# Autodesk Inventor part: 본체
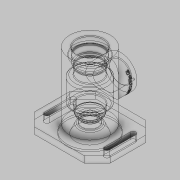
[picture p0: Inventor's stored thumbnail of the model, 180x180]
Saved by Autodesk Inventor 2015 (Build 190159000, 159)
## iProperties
Created: 2017-10
Part Number: 본체
Material: 일반
Document SubType Name: Modeling
Designer: SCD-A15
Density: 1 g/cm^3
Appearance: 기본값
Author: SCD-A15
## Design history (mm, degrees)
sketch "스케치1"
  geometry: L1 (31, 57.5)-(0, 57.5); L2 (0, 57.5)-(0, -57.5); L3 (0, -57.5)-(31, -57.5); L4 (31, -57.5)-(31, 57.5); 2 further points
  constraints: 8 end point, 2 coincident, 2 parallel, 1 horizontal, 1 midpoint, 1 perpendicular
  dimensions: "d0" = 115 distance of L3.end L1.start; "d2" = 62 diameter of L4 L2
revolve "회전1" sketch "스케치1" stored, may be unused: angle "d3" = 90 deg
sketch "스케치2"
  geometry: L1 (-58, 47)-(58, 47); L2 (58, 47)-(58, -47); L3 (58, -47)-(-58, -47); L4 (-58, -47)-(-58, 47); C1 r 31 at (0, 0) reference; 2 further points
  constraints: 8 end point, 2 midpoint, 2 parallel, 1 horizontal, 1 horizontal alignment, 1 perpendicular, 1 vertical alignment
  dimensions: "d5" = 116 distance of L1.start L1.end; "d6" = 94 distance of L3.end L1.start
extrude "돌출1" join sketch "스케치2" distance "d7" = 13; taper "d8" = 0 deg
sketch "스케치3"
  geometry: L1 (0, 0)-(116, 0) reference; L2 (0, -94)-(0, 0) reference; L3 (116, -94)-(0, -94) reference; L4 (116, 0)-(116, -94) reference; C1 r 35 at (58, -47); 1 further point
  constraints: 1 centre point, 1 coincident
  dimensions: "d9" = 70 diameter of C1
extrude "돌출2" cut sketch "스케치3" distance "d10" = 3; taper "d11" = 0 deg
node "작업 평면2"
  node "작업 평면1"
sketch "스케치4"
  geometry: L1 (89, -102)-(27, -102) reference; C1 r 25 at (58, -46); 2 further points
  constraints: 1 centre point, 1 midpoint, 1 vertical alignment
  dimensions: "d13" = 50 diameter of C1; "d14" = 56 distance from line of L1 C1.centre
extrude "돌출3" join sketch "스케치4" stored distance "d15" = 47 (= d12); taper "d16" = 0 deg
sketch "스케치5" dims "d17" = 8, "d18" = 8
  geometry: L1 (46.253, 16.008)-(46.154, 16.008); L2 (46.154, -16.003)-(46.253, -16.003); C1 r 31 at (0, 0) reference; 2 further points
  constraints: 4 end point, 1 horizontal, 1 parallel, 1 vertical alignment, 6 other
  dimensions: "d19" = 46 horizontal distance of C1.centre point (46, -20); "d20" = 20 vertical distance of C1.centre point (46, -20); "d22" = 20 vertical distance of point (46, 20) C1.centre
extrude "돌출4" cut sketch "스케치5" distance "d23" = 47 (= d12); taper "d24" = 0 deg
sketch "스케치6"
  geometry: L1 (42, 20)-(50, 20); L2 (50, 20)-(50, -20); L3 (50, -20)-(42, -20); L4 (42, -20)-(42, 20); 2 further points
  constraints: 8 end point, 2 horizontal alignment, 2 parallel, 1 horizontal, 1 perpendicular, 2 other
extrude "돌출5" cut sketch "스케치6" distance "d25" = 47 (= d12); taper "d26" = 0 deg
hole "구멍1" diameter "d29" = 40.376; stored, may be unused: countersink angle "d33" = 90 deg, drill point angle "d35" = 0 deg; dims "d30" = 84, "d31" = 4, "d32" = 2, "d34" = 9, "d55" = 10, "d56" = 10
hole "구멍2" diameter "d38" = 48; stored, may be unused: countersink angle "d42" = 90 deg, drill point angle "d44" = 0 deg; dims "d36" = 10, "d37" = 10, "d39" = 84, "d40" = 4, "d41" = 2, "d43" = 3
sketch "스케치9"
  geometry: L1 (-35, -57.5)-(-35, -54.5) reference; L2 (-35, -54.5)-(-47, -54.5) reference; L3 (-47, -54.5)-(-47, -44.5) reference; L4 (-47, -44.5)-(-31, -44.5) reference; L5 (-31, -44.5)-(-31, 57.5) reference; L6 (-31, 57.5)-(-20.188, 57.5) reference; L7 (-20.188, 57.5)-(-20.188, 48.5) reference; L8 (-20.188, 48.5)-(-24, 48.5) reference; L9 (-24, 48.5)-(-24, 45.5) reference; L10 (-24, 45.5)-(24, 45.5) reference; L11 (24, 45.5)-(24, 48.5) reference; L12 (24, 48.5)-(20.188, 48.5) reference; L13 (20.188, 48.5)-(20.188, 57.5) reference; L14 (20.188, 57.5)-(31, 57.5) reference; L15 (31, 57.5)-(31, 26.5) reference; L16 (31, 26.5)-(47, 26.5) reference; L17 (47, 26.5)-(47, -23.5) reference; L18 (47, -23.5)-(31, -23.5) reference; L19 (31, -23.5)-(31, -44.5) reference; L20 (31, -44.5)-(47, -44.5) reference; L21 (47, -44.5)-(47, -54.5) reference; L22 (47, -54.5)-(35, -54.5) reference; L23 (35, -54.5)-(35, -57.5) reference; L24 (35, -57.5)-(-35, -57.5) reference; L25 (20, 45.5)-(20, 36.5); L26 (20, 36.5)-(17.5, 36.5); L27 (17.5, 36.5)-(17.5, 33.25); L28 (0, 45.5)-(0, -57.5); L29 (17.5, 33.25)-(18.5, 33.25); L30 (18.5, 33.25)-(18.5, 31.5); L31 (18.5, 31.5)-(17.5, 31.5); L32 (17.5, 31.5)-(17.5, 20.5); L33 (17.5, 20.5)-(26, 20.5); L34 (26, 20.5)-(26, -17.5); L35 (26, -17.5)-(17.5, -17.5); L36 (17.5, -17.5)-(17.5, -28.5); L37 (17.5, -28.5)-(16.5, -28.5); L38 (16.5, -28.5)-(16.5, -33.5); L39 (16.5, -33.5)-(10, -33.5); L40 (10, -33.5)-(10, -36.2); L41 (10, -36.2)-(12.5, -36.2); L42 (12.5, -36.2)-(12.5, -43.5); L43 (12.904, -43.5)-(16, -43.5); L44 (16, -43.5)-(22, -57.5); L45 (12.5, -42.8)-(12.904, -43.5); 1 further point
  constraints: 42 end point, 11 perpendicular, 6 horizontal, 3 point on line, 2 midpoint, 1 vertical
  dimensions: "d47" = 40 diameter of L25 L28; "d48" = 35 diameter of L27 L28; "d49" = 9 distance of L25.start L25.end; "d50" = 3.25 distance of L26.end L27.end; "d51" = 1.75 distance of L29.end L30.end; "d52" = 37 diameter of L30 L28; "d53" = 11 distance of L31.end L32.end; "d54" = 35 diameter of L32 L28; "d59" = 38 distance of L33.end L34.end; "d60" = 52 diameter of L34 L28; "d61" = 35 diameter of L36 L28; "d62" = 11 distance of L35.end L36.end; "d63" = 5 distance of L37.end L38.end; "d64" = 33 diameter of L38 L28; "d66" = 2.7 distance of L39.end L40.end; "d67" = 20 diameter of L40 L28; "d68" = 25 diameter of L42 L28; "d69" = 7.3 distance of L41.end L42.end; "d70" = 32 diameter of L43.end L28; "d71" = 44 diameter of L44.end L28; "d72" = 0.7 distance from line of L43 L45.start; "d73" = 30 deg angle of L42 L45
revolve "회전2" sketch "스케치9" stored, may be unused: angle "d74" = 90 deg
sketch "스케치10"
  geometry: C1 r 25 at (0, 0) reference; C2 r 16 at (0, 0); 1 further point
  constraints: 1 centre point, 1 coincident
  dimensions: "d75" = 32 diameter of C2
extrude "돌출6" cut sketch "스케치10" stored distance "d76" = 47 (= d12); taper "d77" = 0 deg
sketch "스케치12"
  geometry: L1 (31, -56)-(-31, -56) reference; C1 r 16 at (0, 0) reference; 3 further points
  dimensions: "d82" = 20.5 distance of C1.centre point (-20.5, 0); "d83" = 56 distance from line of L1 point (-20.5, 0); "d84" = 20.5 distance of C1.centre point (20.5, 0); "d85" = 56 distance from line of L1 point (20.5, 0)
hole "구멍3" sketch "스케치12" at (-20.5, 0), (20.5, 0) diameter "d86" = 2.459; stored, may be unused: countersink angle "d90" = 90 deg, drill point angle "d92" = 118 deg; dims "d87" = 6, "d88" = 4, "d89" = 2, "d91" = 8
node "작업 평면3"
sketch "스케치13"
  geometry: L1 (-31, 57.5)-(31, 57.5) reference; L2 (47, 26.5)-(47, -23.5) reference; 2 further points
  constraints: 1 other
  dimensions: "d94" = 56 distance from line of L1 point (37, 1.5); "d95" = 10 distance from line of L2 point (37, 1.5)
feature "엠보싱1" sketch "스케치13" dims "d0" = 115, "d2" = 62, "d96" = 0.5, "d97" = 0
chamfer "모따기1" distance "d78" = 20; stored, may be unused: second distance "d79" = 2, angle "d80" = 45 deg
chamfer "모따기2" distance "d98" = 1; stored, may be unused: second distance "d99" = 2, angle "d100" = 45 deg
fillet "모깎기1" dims "d101" = 2
fillet "모깎기2" dims "d102" = 3
chamfer "모따기3" distance "d103" = 1; stored, may be unused: second distance "d104" = 2, angle "d105" = 45 deg
fillet "모깎기3" dims "d106" = 0.3
fillet "모깎기4" dims "d107" = 0.3
node "작업 평면4"
node "솔리드1"
mirror "대칭1"
node "절단 모서리 투영1"
other parameters: "d12" = 47, "d93" = 81.5
